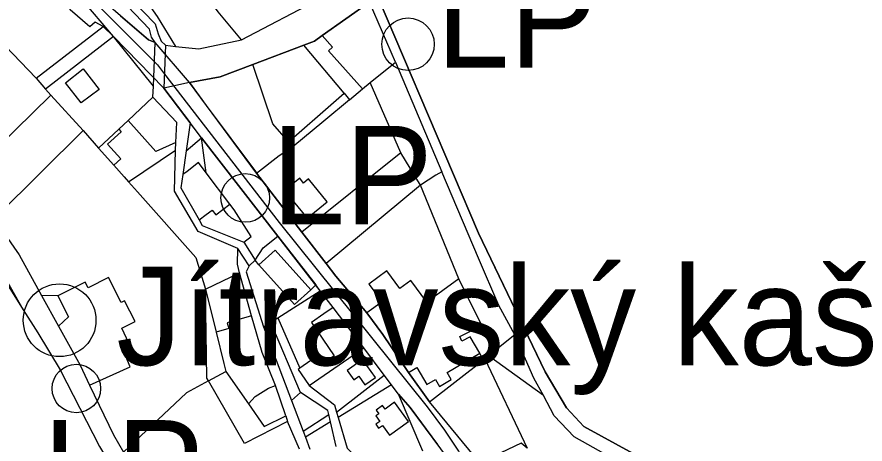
# Model space of a CAD drawing. Extents: x -706771 to -698463, y -971709 to -967107.
# Drawn here: x -701879.1 to -701534.9, y -969544.9 to -969371.6 of the extents above; entities that cross this region are included whole.
import ezdxf

# ---------------------------------------------------------------- set-up
doc = ezdxf.new("R2010")
doc.units = 0
for name, color, linetype in [('_hranice krajinny raz ochrana chrakteru zástavby KR2', 7, 'Continuous'), ('_KRAJINNY CELEK', 7, 'Continuous'), ('_KRAJINNY OKRSEK', 7, 'Continuous'), ('KN_Hranice_parcel', 7, 'Continuous'), ('Komunikace III třídy osy S', 7, 'Continuous'), ('Prvky nelesni zeleně zařazené do vyšší ochrany S', 7, 'Continuous'), ('Prvky nelesni zeleně zařazené do vyšší ochrany_popis S', 7, 'Continuous'), ('Prvky nelesní zeleně _dominantní prvky solitérní', 7, 'Continuous'), ('Prvky nelesní zeleně_dominantní aleje', 7, 'Continuous'), ('Trasy cykloturistické N', 7, 'Continuous'), ('Trasy cykloturistické S', 7, 'Continuous'), ('Trasy turistické S', 7, 'Continuous')]:
    doc.layers.add(name, color=color, linetype=linetype)

msp = doc.modelspace()

# ---------------------------------------------------------------- linework, layer by layer
at = {"layer": '_hranice krajinny raz ochrana chrakteru zástavby KR2'}
for p, q in [((-701691.82, -969459.3), (-701732.44, -969363.94)), ((-701664.72, -969515.58), (-701691.82, -969459.3)), ((-701656.12, -969530.16), (-701664.72, -969515.58)), ((-701649.06, -969537.71), (-701656.12, -969530.16)), ((-701629.05, -969548.66), (-701649.06, -969537.71))]:
    msp.add_line(p, q, dxfattribs=at)
at = {"layer": '_KRAJINNY CELEK'}
msp.add_line((-701732.44, -969363.94), (-701691.82, -969459.3), dxfattribs=at)
for points in [[(-701204.08, -969913.32), (-701235.98, -969882.23), (-701283.43, -969851.5), (-701289.13, -969846.19), (-701305.56, -969829.54), (-701335.51, -969810.18), (-701379.3, -969774.44), (-701462.36, -969724.35), (-701515.1, -969682.84), (-701520.11, -969672.24), (-701554.94, -969649.68), (-701572.31, -969634.51), (-701577.47, -969604.43), (-701578.92, -969587.47), (-701583.19, -969576.91), (-701590.87, -969568.43), (-701629.05, -969548.66), (-701649.06, -969537.71), (-701656.12, -969530.16), (-701664.72, -969515.58), (-701691.82, -969459.3), (-701732.44, -969363.94)], [(-701691.82, -969459.3), (-701664.72, -969515.58), (-701656.12, -969530.16), (-701649.06, -969537.71)], [(-701649.06, -969537.71), (-701629.05, -969548.66), (-701590.87, -969568.43), (-701583.19, -969576.91)]]:
    msp.add_lwpolyline(points, dxfattribs=at)
at = {"layer": '_KRAJINNY OKRSEK'}
for p, q in [((-701732.44, -969363.94), (-701691.82, -969459.3)), ((-701691.82, -969459.3), (-701732.44, -969363.94)), ((-701691.82, -969459.3), (-701664.72, -969515.58)), ((-701664.72, -969515.58), (-701691.82, -969459.3)), ((-701664.72, -969515.58), (-701656.12, -969530.16)), ((-701656.12, -969530.16), (-701664.72, -969515.58)), ((-701656.12, -969530.16), (-701649.06, -969537.71)), ((-701649.06, -969537.71), (-701656.12, -969530.16)), ((-701649.06, -969537.71), (-701629.05, -969548.66))]:
    msp.add_line(p, q, dxfattribs=at)
msp.add_lwpolyline([(-701572.31, -969634.51), (-701577.47, -969604.43), (-701578.92, -969587.47), (-701583.19, -969576.91), (-701590.87, -969568.43), (-701629.05, -969548.66), (-701649.06, -969537.71)], dxfattribs=at)
at = {"layer": 'KN_Hranice_parcel'}
for p, q in [((-701787.98, -969380.88), (-701755.9, -969363.95)), ((-701736.09, -969365.64), (-701755.24, -969379.17)), ((-701725.43, -969390), (-701736.09, -969365.64)), ((-701894, -969373.01), (-701871.41, -969396.45)), ((-701871.41, -969396.45), (-701844.19, -969375.53)), ((-701840, -969379.54), (-701844.19, -969375.53)), ((-701840, -969379.54), (-701867.61, -969400.95)), ((-701823.73, -969399.77), (-701840, -969379.54)), ((-701823.73, -969399.77), (-701822.99, -969381.99)), ((-701818.88, -969383.07), (-701819.57, -969400.53)), ((-701818.88, -969383.07), (-701814.82, -969383.55)), ((-701762.69, -969383.03), (-701783.36, -969390.88)), ((-701746.37, -969402.56), (-701762.69, -969383.03)), ((-701735.82, -969398.26), (-701725.43, -969390)), ((-701725.43, -969390), (-701706.64, -969434.42)), ((-701871.41, -969396.45), (-701867.61, -969400.95)), ((-701867.61, -969400.95), (-701865.37, -969403.37)), ((-701823.92, -969404.18), (-701823.73, -969399.77)), ((-701809.1, -969398.26), (-701819.57, -969400.53)), ((-701819.57, -969400.53), (-701808.87, -969414.52)), ((-701744.18, -969405.19), (-701738.94, -969400.76)), ((-701738.94, -969400.76), (-701735.82, -969398.26)), ((-701723.33, -969426.72), (-701735.82, -969398.26)), ((-701900.8, -969437.89), (-701865.37, -969403.37)), ((-701865.37, -969403.37), (-701852.29, -969417.71)), ((-701833.98, -969413.57), (-701823.92, -969404.18)), ((-701746.37, -969402.56), (-701744.18, -969405.19)), ((-701833.98, -969413.57), (-701837.78, -969417.12)), ((-701808.87, -969414.52), (-701810.49, -969425.94)), ((-701804.18, -969420.66), (-701808.87, -969414.52)), ((-701888.47, -969453.58), (-701852.29, -969417.71)), ((-701852.29, -969417.71), (-701846, -969424.79)), ((-701846, -969424.79), (-701837.78, -969417.12)), ((-701810.49, -969425.94), (-701804.18, -969420.66)), ((-701802.31, -969434.88), (-701804.18, -969420.66)), ((-701804.18, -969420.66), (-701773.24, -969460.57)), ((-701846, -969424.79), (-701839.78, -969431.79)), ((-701814.72, -969425.68), (-701814.6, -969422.54)), ((-701767.16, -969424.32), (-701768.97, -969422.25)), ((-701833.81, -969438.52), (-701814.72, -969425.68)), ((-701810.49, -969425.94), (-701811.85, -969435.57)), ((-701723.33, -969426.72), (-701763.53, -969458.9)), ((-701715.3, -969439.83), (-701723.33, -969426.72)), ((-701792.69, -969447.61), (-701802.31, -969434.88)), ((-701781.95, -969434.96), (-701763.53, -969458.9)), ((-701715.3, -969439.83), (-701753.63, -969471.61)), ((-701699.84, -969477.81), (-701715.3, -969439.83)), ((-701763.53, -969458.9), (-701753.63, -969471.61)), ((-701787.11, -969463.04), (-701782.39, -969470.32)), ((-701773.24, -969460.57), (-701757.85, -969480.31)), ((-701784.87, -969472.6), (-701789.47, -969465.57)), ((-701782.39, -969470.32), (-701784.87, -969472.6)), ((-701780.95, -969472.14), (-701782.39, -969470.32)), ((-701802.65, -969482), (-701788.74, -969475.41)), ((-701783.91, -969492.89), (-701788.74, -969475.41)), ((-701757.85, -969480.31), (-701759.91, -969482.36)), ((-701756.05, -969482.66), (-701757.85, -969480.31)), ((-701802.65, -969482), (-701798.28, -969499.5)), ((-701773.18, -969493.62), (-701756.05, -969482.66)), ((-701750.84, -969489.45), (-701756.05, -969482.66)), ((-701862.54, -969484.73), (-701869.12, -969484.61)), ((-701869.12, -969484.61), (-701862.26, -969497.02)), ((-701738.28, -969505.82), (-701750.84, -969489.45)), ((-701776.13, -969495.51), (-701773.18, -969493.62)), ((-701773.18, -969493.62), (-701764.28, -969514.07)), ((-701779.03, -969497.36), (-701776.13, -969495.51)), ((-701779.03, -969497.36), (-701767.72, -969527.23)), ((-701764, -969523.94), (-701776.13, -969495.51)), ((-701677.02, -969500.53), (-701687.7, -969509.05)), ((-701760.46, -969521.16), (-701738.28, -969505.82)), ((-701730.03, -969516.92), (-701738.28, -969505.82)), ((-701689.89, -969510.8), (-701691.26, -969507.99)), ((-701711.65, -969527.7), (-701689.89, -969510.8)), ((-701689.27, -969510.3), (-701689.89, -969510.8)), ((-701687.7, -969509.05), (-701689.27, -969510.3)), ((-701689.27, -969510.3), (-701671.98, -969546.5)), ((-701665.46, -969525.24), (-701687.7, -969509.05)), ((-701801.43, -969519.27), (-701794.31, -969515.44)), ((-701794.31, -969515.44), (-701785.18, -969528.52)), ((-701749.43, -969531.9), (-701730.03, -969516.92)), ((-701727.11, -969520.81), (-701730.03, -969516.92)), ((-701720.21, -969515.81), (-701711.65, -969527.7)), ((-701801.43, -969519.27), (-701810.34, -969524.05)), ((-701770.03, -969533.45), (-701774.18, -969521.13)), ((-701727.11, -969520.81), (-701748.79, -969534.04)), ((-701724.26, -969524.59), (-701727.11, -969520.81)), ((-701810.34, -969524.05), (-701835.87, -969548.13)), ((-701767.72, -969527.23), (-701764, -969523.94)), ((-701714.33, -969547.79), (-701724.26, -969524.59)), ((-701767.72, -969527.23), (-701763.02, -969539.63)), ((-701691.2, -969552.48), (-701711.65, -969527.7)), ((-701749.43, -969531.9), (-701748.79, -969534.04)), ((-701770.03, -969533.45), (-701769.28, -969535.66)), ((-701764.49, -969547.01), (-701769.28, -969535.66)), ((-701763.02, -969539.63), (-701752.52, -969532.86)), ((-701751.84, -969535.9), (-701752.52, -969532.86)), ((-701751.84, -969535.9), (-701762.07, -969542.14)), ((-701749.63, -969545.8), (-701751.84, -969535.9)), ((-701763.02, -969539.63), (-701762.07, -969542.14)), ((-701762.07, -969542.14), (-701760.24, -969546.98))]:
    msp.add_line(p, q, dxfattribs=at)
for points in [[(-701787.98, -969380.88), (-701797.41, -969369.52), (-701800.26, -969365.57), (-701806.42, -969357.03), (-701812.08, -969349.27), (-701818.12, -969340.93)], [(-701846.16, -969345.07), (-701837.43, -969359.57), (-701823.02, -969374.42), (-701821.83, -969378.46), (-701820.55, -969381.43), (-701818.88, -969383.07)], [(-701844.19, -969375.53), (-701847.45, -969373.72), (-701849.62, -969375.68), (-701857.56, -969368.8), (-701866.19, -969348.55)], [(-701835.14, -969353), (-701822.21, -969371.44), (-701814.82, -969383.55)], [(-701572.31, -969634.51), (-701576.12, -969609.1), (-701577.47, -969604.43), (-701577.53, -969603.89), (-701578.24, -969598.49), (-701578.63, -969598.11), (-701578.92, -969587.47), (-701583.19, -969576.91), (-701590.87, -969568.43), (-701599.55, -969563.27), (-701612.37, -969556.92), (-701629.05, -969548.66), (-701649.06, -969537.71), (-701656.12, -969530.16), (-701664.72, -969515.58), (-701673.38, -969497.63), (-701691.82, -969459.3), (-701732.44, -969363.94)], [(-701822.99, -969381.99), (-701824.55, -969379.88), (-701825.39, -969376.52), (-701834.22, -969367.32)], [(-701837.05, -969371.22), (-701825.7, -969380.96), (-701822.99, -969381.99)], [(-701755.24, -969379.17), (-701758.38, -969381.39), (-701762.69, -969383.03)], [(-701738.94, -969400.76), (-701752.67, -969385.36), (-701751.02, -969383.9), (-701755.24, -969379.17)], [(-701814.82, -969383.55), (-701805.28, -969384.57), (-701787.98, -969380.88)], [(-701783.36, -969390.88), (-701796.72, -969395.96), (-701809.1, -969398.26)], [(-701768.97, -969422.25), (-701775.26, -969415.03), (-701783.36, -969390.88)], [(-701859.37, -969398.3), (-701852.22, -969392.73), (-701845.83, -969400.99), (-701853.03, -969406.52), (-701859.37, -969398.3)], [(-701809.1, -969398.26), (-701802.37, -969407.61), (-701782.35, -969434.38), (-701781.95, -969434.96)], [(-701814.6, -969422.54), (-701814.29, -969414.38), (-701823.92, -969404.18)], [(-701768.97, -969422.25), (-701750.7, -969406.33), (-701746.37, -969402.56)], [(-701744.18, -969405.19), (-701754.51, -969413.91), (-701767.16, -969424.32)], [(-701814.6, -969422.54), (-701822.75, -969426.22), (-701833.98, -969413.57)], [(-701932.15, -969417.65), (-701916.27, -969433.11), (-701905.5, -969448.18), (-701892.43, -969465.33), (-701881.94, -969481.12), (-701876.57, -969490.41), (-701870.6, -969499.82), (-701861.62, -969514.7), (-701845.58, -969545.8), (-701835.67, -969562.49), (-701832.77, -969566.66)], [(-701837.78, -969417.12), (-701836.81, -969418.18), (-701842.34, -969423.25), (-701836.91, -969429.16), (-701839.78, -969431.79)], [(-701781.95, -969434.96), (-701772.69, -969427.86), (-701767.16, -969424.32)], [(-701789.47, -969465.57), (-701805.53, -969458.67), (-701815.25, -969442.27), (-701814.72, -969425.68)], [(-701839.78, -969431.79), (-701835.64, -969436.46), (-701833.81, -969438.52)], [(-701802.31, -969434.88), (-701805.44, -969430.73), (-701810.11, -969434.26), (-701811.85, -969435.57)], [(-701811.85, -969435.57), (-701812.61, -969440.91), (-701805.2, -969453.92)], [(-701706.64, -969434.42), (-701709.09, -969435.86), (-701715.3, -969439.83)], [(-701677.02, -969500.53), (-701683.51, -969488.67), (-701691.84, -969469.5), (-701706.64, -969434.42)], [(-701833.81, -969438.52), (-701830.16, -969442.62), (-701806.58, -969469.19), (-701802.65, -969482)], [(-701762.77, -969439), (-701764.38, -969437.03), (-701770.52, -969442.04), (-701765.13, -969448.64), (-701761.39, -969453.23), (-701753.23, -969446.57), (-701760.75, -969437.35), (-701762.77, -969439)], [(-701805.2, -969453.92), (-701802.31, -969451.73), (-701799.95, -969449.95), (-701798.44, -969451.95), (-701792.69, -969447.61)], [(-701787.11, -969463.04), (-701784.12, -969460.74), (-701790.96, -969449.83), (-701792.69, -969447.61)], [(-701888.47, -969453.58), (-701878.24, -969468.09), (-701869.12, -969484.61)], [(-701805.2, -969453.92), (-701803.92, -969456.17), (-701787.11, -969463.04)], [(-701782.39, -969470.32), (-701779.19, -969465.27), (-701773.24, -969460.57)], [(-701788.74, -969475.41), (-701789.58, -969471.91), (-701789.47, -969465.57)], [(-701759.91, -969482.36), (-701774.39, -969466.23), (-701780.95, -969472.14)], [(-701784.87, -969472.6), (-701786.04, -969475.08), (-701779.03, -969497.36)], [(-701780.95, -969472.14), (-701766.45, -969488.23), (-701759.91, -969482.36)], [(-701753.63, -969471.61), (-701749.65, -969476.72), (-701737.07, -969491.71)], [(-701699.84, -969477.81), (-701712.81, -969487.38), (-701719.29, -969478.59), (-701723.68, -969481.83), (-701729.02, -969474.59), (-701736.3, -969479.96), (-701730.95, -969487.2), (-701737.07, -969491.71)], [(-701849.71, -969520.92), (-701833.13, -969513.55), (-701835, -969509.34), (-701831.84, -969507.95), (-701836.63, -969497.91), (-701831.17, -969495.17), (-701835.42, -969486.71), (-701836.9, -969487.45), (-701841.98, -969477.32), (-701850.29, -969481.49), (-701851.46, -969479.17), (-701862.54, -969484.73)], [(-701691.26, -969507.99), (-701695.24, -969501.34), (-701698.53, -969503.12), (-701699.38, -969501.2), (-701690.4, -969496.73), (-701696.93, -969483.65), (-701699.84, -969477.81)], [(-701801.43, -969519.27), (-701802.1, -969518.11), (-701802.65, -969482)], [(-701862.54, -969484.73), (-701858.24, -969493.31), (-701862.26, -969497.02)], [(-701750.84, -969489.45), (-701754.58, -969492.04), (-701759.6, -969495.51), (-701750.35, -969509.06), (-701754.54, -969511.96), (-701756.7, -969508.83), (-701764.28, -969514.07)], [(-701783.91, -969492.89), (-701793.86, -969495.74), (-701793.2, -969498.05), (-701798.28, -969499.5)], [(-701774.18, -969521.13), (-701779.66, -969507.74), (-701783.91, -969492.89)], [(-701737.07, -969491.71), (-701730.56, -969500.48), (-701720.21, -969515.81)], [(-701862.26, -969497.02), (-701853.48, -969512.92), (-701849.71, -969520.92)], [(-701798.28, -969499.5), (-701795.12, -969512.17), (-701794.31, -969515.44)], [(-701665.46, -969525.24), (-701669.28, -969518.21), (-701677.02, -969500.53)], [(-701720.21, -969515.81), (-701716.83, -969513.83), (-701712.8, -969520.72), (-701709.3, -969518.66), (-701707.61, -969521.55), (-701702.83, -969518.75), (-701704.53, -969515.84), (-701691.26, -969507.99)], [(-701745.09, -969514.99), (-701742.36, -969518.8), (-701740.4, -969517.4), (-701737.9, -969520.88), (-701733.65, -969517.84), (-701738.88, -969510.54), (-701745.09, -969514.99)], [(-701764.28, -969514.07), (-701765.01, -969514.58), (-701760.74, -969520.75), (-701760.46, -969521.16)], [(-701849.71, -969520.92), (-701840.01, -969541.19), (-701835.87, -969548.13)], [(-701769.28, -969535.66), (-701786.82, -969544.64), (-701801.43, -969519.27)], [(-701785.18, -969528.52), (-701782.48, -969525.53), (-701777, -969522.24), (-701774.18, -969521.13)], [(-701760.46, -969521.16), (-701750.31, -969528.96), (-701749.43, -969531.9)], [(-701752.52, -969532.86), (-701752.89, -969531.22), (-701764, -969523.94)], [(-701724.26, -969524.59), (-701719.56, -969530.1), (-701708.4, -969545.08)], [(-701631.92, -969553.64), (-701653.02, -969541.94), (-701661.01, -969533.45), (-701665.46, -969525.24)], [(-701785.18, -969528.52), (-701778.78, -969537.7), (-701770.03, -969533.45)], [(-701725.9, -969527.92), (-701729.74, -969530.72), (-701730.8, -969529.26), (-701733.35, -969531.11), (-701732.29, -969532.57), (-701733.5, -969533.45), (-701731.88, -969535.68), (-701733.5, -969536.85), (-701732.32, -969538.47), (-701730.7, -969537.29), (-701727.85, -969541.21), (-701720.25, -969535.68), (-701725.9, -969527.92)], [(-701748.79, -969534.04), (-701745.06, -969546.49), (-701733.7, -969557.69)], [(-701671.98, -969546.5), (-701674.53, -969544.53), (-701691.2, -969552.48)]]:
    msp.add_lwpolyline(points, dxfattribs=at)
at = {"layer": 'Komunikace III třídy osy S'}
msp.add_lwpolyline([(-701848.39, -969364.65), (-701822.11, -969391.05), (-701819.6, -969394.24), (-701772.74, -969455.01), (-701712.57, -969529.74), (-701705.62, -969539.23), (-701699.9, -969547.78), (-701697.01, -969552.85), (-701687.35, -969572.61), (-701675.94, -969595.35), (-701673.16, -969599.86), (-701662.47, -969613.35), (-701647.7, -969638.23), (-701630.07, -969671.39), (-701617.42, -969695.2), (-701595.58, -969734.39), (-701592.55, -969740.63), (-701588.15, -969750.17), (-701584.61, -969759.38), (-701576.21, -969783.3), (-701573.35, -969789.63), (-701571.43, -969793), (-701569.73, -969795.62), (-701567.09, -969798.56)], dxfattribs=at)
at = {"layer": 'Prvky nelesni zeleně zařazené do vyšší ochrany S'}
msp.add_circle((-701861.82, -969494.66), 14.76, dxfattribs=at)
at = {"layer": 'Prvky nelesní zeleně _dominantní prvky solitérní'}
for centre, radius in [((-701720.39, -969382.7), 10.65), ((-701786.47, -969445.04), 9.87), ((-701855.01, -969522.35), 9.84)]:
    msp.add_circle(centre, radius, dxfattribs=at)
at = {"layer": 'Prvky nelesní zeleně_dominantní aleje'}
msp.add_lwpolyline([(-701916.27, -969433.11), (-701892.43, -969465.33), (-701876.57, -969490.41)], dxfattribs=at)
at = {"layer": 'Trasy cykloturistické N'}
msp.add_lwpolyline([(-701809.1, -969398.26), (-701796.72, -969395.96), (-701783.36, -969390.88), (-701762.69, -969383.03), (-701758.38, -969381.39), (-701755.24, -969379.17), (-701736.09, -969365.64), (-701732.44, -969363.94), (-701716, -969350.87), (-701678.6, -969319.48), (-701639.64, -969286.88), (-701601.2, -969253.94), (-701561.71, -969220.76), (-701527.04, -969191.82), (-701486.19, -969156.31), (-701464.83, -969137.71), (-701459.95, -969135.78), (-701438.74, -969125.05), (-701410.21, -969107.23), (-701360.12, -969070.31), (-701329.09, -969047.29), (-701290.25, -969018.1), (-701242.42, -968984.02)], dxfattribs=at)
at = {"layer": 'Trasy cykloturistické S'}
msp.add_lwpolyline([(-701697.79, -969559.33), (-701719.56, -969530.1), (-701724.26, -969524.59), (-701730.03, -969516.92), (-701738.28, -969505.82), (-701750.84, -969489.45), (-701756.05, -969482.66), (-701773.24, -969460.57), (-701804.18, -969420.66), (-701819.57, -969400.53), (-701840, -969379.54), (-701866.19, -969348.55)], dxfattribs=at)
at = {"layer": 'Trasy turistické S'}
msp.add_line((-701809.1, -969398.26), (-701822.99, -969381.99), dxfattribs=at)
for points in [[(-701822.99, -969381.99), (-701825.7, -969380.96), (-701837.05, -969371.22), (-701847.18, -969362.37), (-701850.36, -969358.69), (-701864.41, -969338.95), (-701869.57, -969331.44), (-701877.94, -969319.13), (-701882.6, -969312.69)], [(-701691.2, -969552.48), (-701711.65, -969527.7), (-701720.21, -969515.81), (-701730.56, -969500.48), (-701737.07, -969491.71), (-701749.65, -969476.72), (-701753.63, -969471.61), (-701763.53, -969458.9), (-701781.95, -969434.96), (-701809.1, -969398.26)]]:
    msp.add_lwpolyline(points, dxfattribs=at)

# ---------------------------------------------------------------- texts
at = {"layer": 'Prvky nelesni zeleně zařazené do vyšší ochrany_popis S'}
msp.add_text('Jítravský kaštan', height=40, dxfattribs=at).set_placement((-701838.81, -969512.89))
at = {"layer": 'Prvky nelesní zeleně _dominantní prvky solitérní'}
for p in [(-701709, -969392.23), (-701775.76, -969455.8), (-701868.63, -969575.18)]:
    msp.add_text('LP', height=40, dxfattribs=at).set_placement(p)

doc.saveas('drawing.dxf')
